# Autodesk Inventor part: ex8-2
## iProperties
Author: Administrator
Created: 2001-03
Part Number: ex8-2
Document SubType Name: Modeling
Designer: Administrator
Control State: 0
Master: False
Checked Out: False
PropertySet Name: Design Tracking Control
Shininess: 20.0
Length Units: 11272
Angle Units: 11286
Time Units: 11279
Mass Units: 11290
Length Display Precision: 3
Angle Display Precision: 2
Compacted: False
PropertySet Name: _Private Model Information
Density: 0.0
Volumn: 0.0
Area: 0.0
PropertySet Name: Model Information
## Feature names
1. Extrusion1
2. Extrusion2
